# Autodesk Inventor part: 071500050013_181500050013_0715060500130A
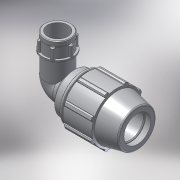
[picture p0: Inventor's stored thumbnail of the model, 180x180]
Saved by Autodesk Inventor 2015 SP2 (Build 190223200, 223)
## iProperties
Created: 2017-02
Part Number: 071500050013_181500050013_0715060500130A
Material: PVC-Piping
Description: PLASSON 90° ELBOW FEMALE ADAPTOR 50-1.1/4"
Document SubType Name: Modeling
Designer: KIM
Mass: 92.6774 g
Surface Area: 199.44 cm^2
Volume: 66.1981 cm^3
Density: 1.4 g/cm^3
Appearance: Smooth - White
Author: KIM
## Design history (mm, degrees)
derived "07150.ipt"
feature "Solid1::07150.ipt"
tag "TaggingFeature1"
body "Solid1"
other parameters: "d4" = 11.08333, "d5" = 33.25, "d7" = 96, "d9" = 19, "d11" = 4.43333, "d13" = 120 deg, "d15" = 12 deg, "d16" = 83.52, "d18" = 2.5, "d19" = 35 deg, "d20" = 17.5 deg, "d21" = 89.28, "d23" = 0, "d25" = 360 deg, "d27" = 1.92, "d33" = 1, "d42" = 49.21, "d43" = 2.88, "d46" = 1.5, "d51" = 133, "d68" = 4.43333, "d72" = 67, "d73" = 50.6376, "d74" = 25, "d75" = 58.23324, "d76" = 38.952, "d77" = 27.5, "d79" = 15.5808, "d80" = 1.16856, "d83" = 0, "d84" = 0, "d91" = 72, "d93" = 93, "d94" = 38.952, "d95" = 27.2664, "d96" = 13.3, "d97" = 50 deg, "d98" = 35.0568, "d99" = 0.5, "d100" = 0.5, "d101" = 8.33333, "d102" = 50.6376, "d103" = 21.25, "d104" = 0, "d108" = 360 deg, "d110" = 1.51913, "E_" = 96, "A_" = 133, "l_" = 93, "l_2" = 25, "A_1" = 67, "Rp_" = 38.952, "d105" = 7.59564
